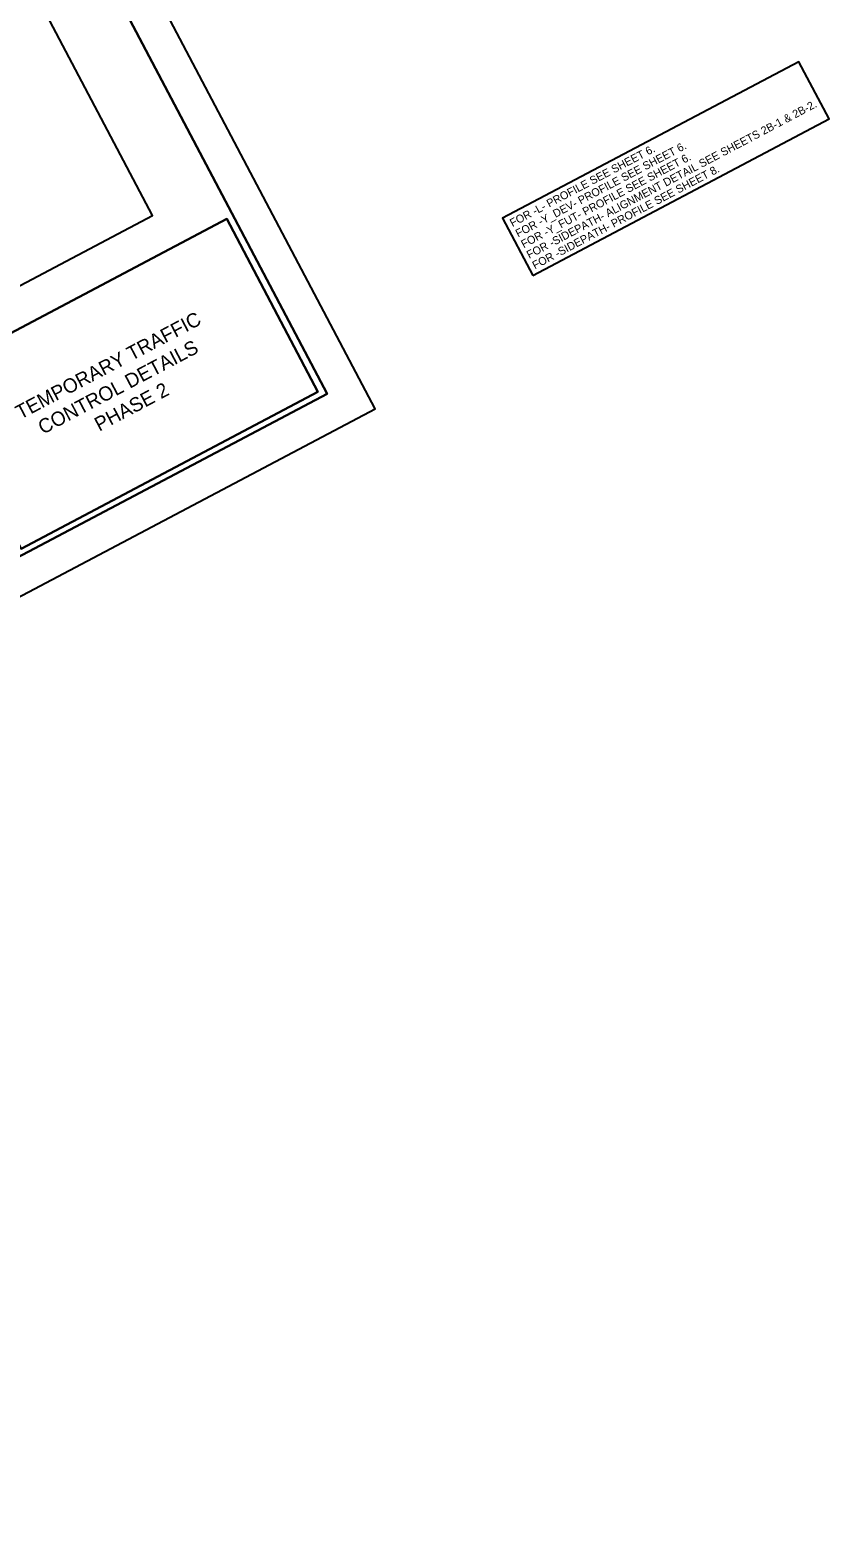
# Model space of a CAD drawing. Extents: x 1487052 to 1489663, y 496209 to 500965.
# Drawn here: x 1489101 to 1489663, y 497981 to 499036 of the extents above; entities that cross this region are included whole.
import ezdxf

# ---------------------------------------------------------------- set-up
doc = ezdxf.new("R2010")
doc.units = 0
for name, color, linetype in [('DEV TYPE 3 BARRICADE SINGLE WITH R11-2 CELL', 7, 'Continuous'), ('Prop Grid Mask', 7, 'Continuous'), ('Prop Horizontal Alignment Curve and Spiral Data', 7, 'Continuous'), ('Scratch_Level_0', 7, 'Continuous'), ('Scratch_Level_3', 7, 'Continuous'), ('Sheet Plot Border Outside CELL', 7, 'Continuous'), ('WZ OSDR CELL', 7, 'Continuous')]:
    doc.layers.add(name, color=color, linetype=linetype)

msp = doc.modelspace()

# ---------------------------------------------------------------- linework, layer by layer
at = {"layer": 'DEV TYPE 3 BARRICADE SINGLE WITH R11-2 CELL'}
msp.add_lwpolyline([(1488799.3, 499640.6), (1487561.2, 498986.9), (1488004.8, 498146.9), (1488782, 498557.2), (1488726.8, 498661.8), (1489187.6, 498905.1)], close=True, dxfattribs=at)
at = {"layer": 'Prop Grid Mask'}
msp.add_lwpolyline([(1489455.1, 498863), (1489663.4, 498973), (1489642.1, 499013.2), (1489433.8, 498903.2)], close=True, dxfattribs=at)
at = {"layer": 'Scratch_Level_0'}
for points in [[(1488820.1, 499708.2), (1487493.7, 499007.8), (1487984, 498079.3), (1489310.4, 498779.7)], [(1489239.7, 498902.7), (1489031, 498792.5), (1489095.2, 498670.9), (1489303.9, 498781.1)]]:
    msp.add_lwpolyline(points, close=True, dxfattribs=at)
at = {"layer": 'Scratch_Level_3'}
msp.add_lwpolyline([(1487493.7, 499007.8), (1488662.1, 499625.8), (1488820.1, 499708.2), (1489310.4, 498779.7), (1487984, 498079.3)], close=True, dxfattribs=at)
msp.add_lwpolyline([(1487493.7, 499007.8), (1488662.1, 499625.8), (1488820.1, 499708.2), (1489310.4, 498779.7), (1487984, 498079.3)], close=True, dxfattribs=at)
at = {"layer": 'Sheet Plot Border Outside CELL'}
msp.add_lwpolyline([(1487851.5, 497981.1), (1489344.2, 498769.3), (1488830.6, 499742), (1487337.9, 498953.8)], close=True, dxfattribs=at)
at = {"layer": 'WZ OSDR CELL'}
msp.add_lwpolyline([(1489031, 498792.5), (1489239.7, 498902.7), (1489303.9, 498781.1), (1489095.2, 498670.9)], close=True, dxfattribs=at)

# ---------------------------------------------------------------- texts
at = {"layer": 'Prop Horizontal Alignment Curve and Spiral Data'}
for s, p in [('FOR -SIDEPATH- ALIGNMENT DETAIL SEE SHEETS 2B-1 & 2B-2.', (1489452.5, 498874.6)), ('FOR -Y_DEV- PROFILE SEE SHEET 6.', (1489444.7, 498889.6)), ('FOR -L- PROFILE SEE SHEET 6.', (1489440.7, 498897)), ('FOR -Y_FUT- PROFILE SEE SHEET 6.', (1489448.6, 498882.1)), ('FOR -SIDEPATH- PROFILE SEE SHEET 8.', (1489456.5, 498867.2))]:
    msp.add_text(s, height=5.625, rotation=27.8351, dxfattribs=at).set_placement(p)
at = {"layer": 'Scratch_Level_0'}
for s, p in [('TEMPORARY TRAFFIC', (1489094.6, 498761.5)), ('CONTROL DETAILS', (1489110.4, 498751)), ('PHASE 2', (1489150.1, 498753.1))]:
    msp.add_text(s, height=10, rotation=27.8351, dxfattribs=at).set_placement(p)

doc.saveas('drawing.dxf')
